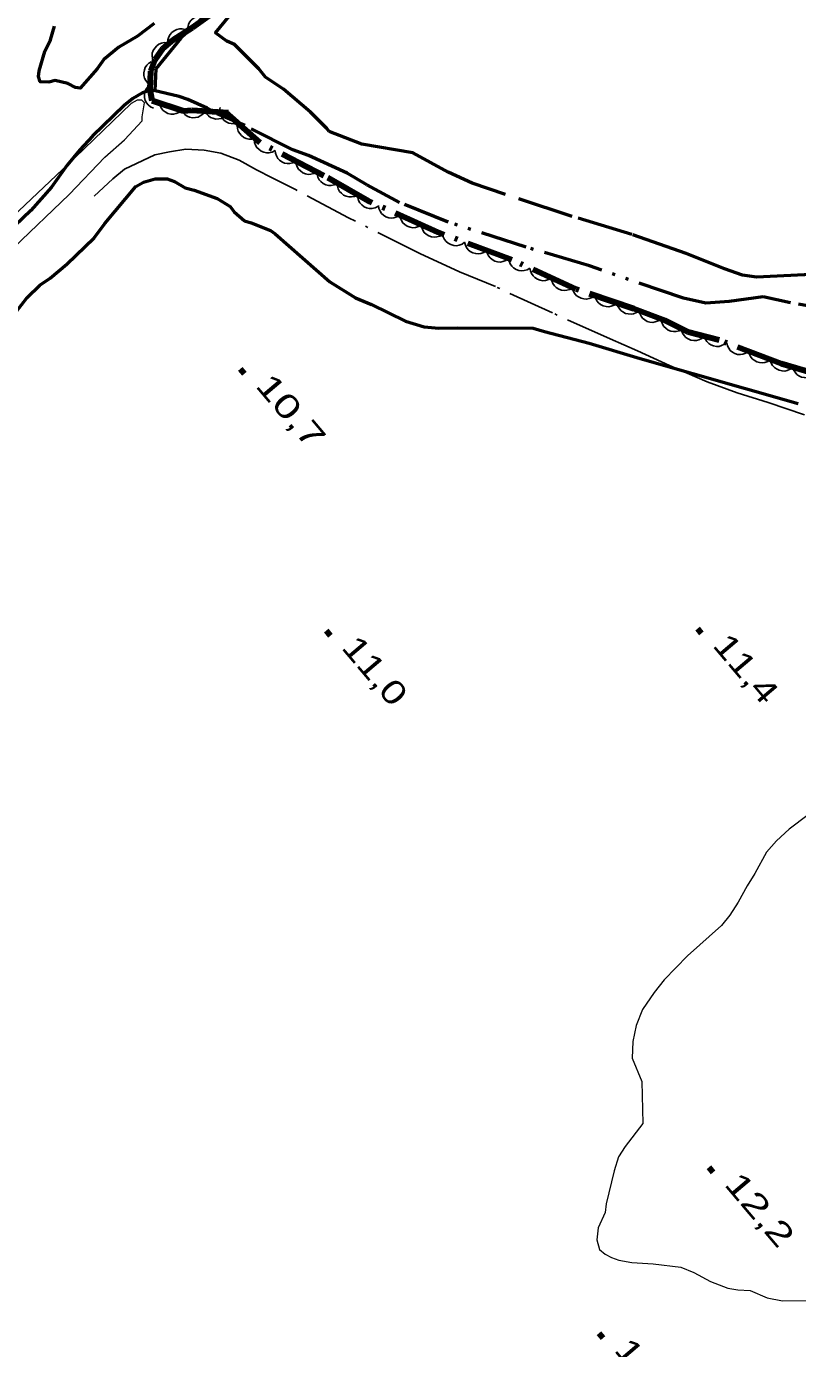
# Model space of a CAD drawing. Extents: x 386081 to 389416, y 5130568 to 5134082.
# Drawn here: x 387029 to 387127.7, y 5132295.3 to 5132464.6 of the extents above; entities that cross this region are included whole.
import ezdxf

# ---------------------------------------------------------------- set-up
doc = ezdxf.new("R2010")
doc.units = 0
doc.header["$LTSCALE"] = 1.2
for name, pattern in [('DASH_DOUBLE_DOT', [9.2, 5, -1.2, 0.3, -1.2, 0.3, -1.2]), ('DOT_DASHED', [7.7, 5, -1.2, 0.3, -1.2]), ('LONG_DASHED', [7.5, 6, -1.5])]:
    doc.linetypes.add(name, pattern=pattern)
for name, color, linetype, lineweight in [('1', 7, 'Continuous', 53), ('2', 7, 'Continuous', 13), ('3', 7, 'Continuous', 140), ('4', 7, 'DASH_DOUBLE_DOT', 53), ('41', 7, 'DOT_DASHED', 25), ('44', 7, 'Continuous', 25)]:
    doc.layers.add(name, color=color, linetype=linetype, lineweight=lineweight)

msp = doc.modelspace()

# ---------------------------------------------------------------- linework, layer by layer
at = {"layer": '1'}
for points in [[(387067.73, 5132451.13), (387067.44, 5132451.51), (387065.37, 5132453.59), (387061.92, 5132456.55), (387059.61, 5132458.09), (387058.74, 5132459.16), (387055.63, 5132462.28), (387054.67, 5132462.68), (387053.22, 5132463.76), (387056.77, 5132468.15)], [(387045.34, 5132464.97), (387043.24, 5132463.34), (387040.83, 5132461.92), (387038.92, 5132460.34), (387038.07, 5132459.17), (387035.9, 5132456.67), (387035.3, 5132456.78), (387034.31, 5132457.28), (387032.69, 5132457.67), (387031.86, 5132457.45), (387030.75, 5132457.51), (387030.54, 5132458.16), (387030.63, 5132458.91), (387031.35, 5132461.38), (387032.1, 5132462.88), (387032.6, 5132464.63)], [(387026.94, 5132427.05), (387029.08, 5132429.87), (387030.7, 5132431.47), (387032.05, 5132432.36), (387034.18, 5132434.15), (387037.66, 5132437.51), (387039.03, 5132439.34), (387043.02, 5132444.11), (387043.97, 5132444.65), (387045.48, 5132445.08), (387047, 5132445.07), (387047.94, 5132444.73)], [(387047.94, 5132444.73), (387049.31, 5132443.9), (387050.49, 5132443.61), (387053.4, 5132442.55), (387055.07, 5132441.54), (387055.57, 5132440.86), (387056.9, 5132439.7), (387057.77, 5132439.46), (387060.22, 5132438.47), (387060.84, 5132438.05), (387067.85, 5132431.87), (387071.11, 5132429.84), (387073.18, 5132428.99), (387077.5, 5132426.87), (387079.91, 5132426.13), (387081.8, 5132425.94), (387084.14, 5132426.01), (387093.87, 5132425.95), (387095.29, 5132425.51), (387101.02, 5132424.05), (387107.54, 5132422.08), (387127.76, 5132416.3)]]:
    msp.add_lwpolyline(points, dxfattribs=at)
at = {"layer": '1', "linetype": 'LONG_DASHED'}
msp.add_lwpolyline([(387145.13, 5132434.28), (387144.46, 5132434.47), (387140.66, 5132435.13), (387139.03, 5132435.07), (387137.56, 5132434.7), (387135.1, 5132433.76), (387132.87, 5132433.3), (387128.58, 5132432.8), (387122.45, 5132432.47), (387120.64, 5132432.76), (387118.34, 5132433.54), (387113.42, 5132435.51), (387106.5, 5132437.95), (387098.86, 5132440.25), (387086.03, 5132444.5), (387082.98, 5132445.94), (387078.46, 5132448.4), (387071.94, 5132449.51), (387067.73, 5132451.13)], dxfattribs=at)
at = {"layer": '2'}
for points in [[(387027.36, 5132436.24), (387034.46, 5132443.05), (387039.02, 5132447.86), (387041.54, 5132450.08), (387043.8, 5132452.5), (387043.81, 5132452.99), (387044.12, 5132454.79), (387043.79, 5132455.16), (387043.19, 5132455.16), (387042.39, 5132454.73), (387035.25, 5132447.8), (387022.35, 5132435.63)], [(387131.47, 5132365.48), (387126.61, 5132361.81), (387124.99, 5132360.33), (387123.74, 5132358.86), (387122.23, 5132356.15), (387121.23, 5132354.56), (387120.1, 5132352.46), (387119.04, 5132350.8), (387117.97, 5132349.51), (387113.61, 5132345.59), (387110.61, 5132342.52), (387109.36, 5132340.93), (387107.86, 5132338.72), (387107.04, 5132336.68), (387106.6, 5132334.65), (387106.52, 5132332.49), (387107.75, 5132329.52), (387107.9, 5132324.16), (387105.65, 5132321.21), (387104.78, 5132319.86), (387104.21, 5132318.07), (387103.19, 5132313.88), (387103.06, 5132312.77), (387102.18, 5132310.8), (387101.99, 5132309.26), (387102.35, 5132308.03), (387103.09, 5132307.41), (387103.9, 5132306.97), (387104.83, 5132306.65), (387106.5, 5132306.34), (387109.23, 5132306.19), (387112.76, 5132305.74), (387114.44, 5132305.05), (387116.54, 5132303.93), (387118.77, 5132303.05), (387120.07, 5132302.86), (387121.62, 5132302.78), (387123.79, 5132301.84), (387125.77, 5132301.46), (387129.19, 5132301.5)]]:
    msp.add_lwpolyline(points, dxfattribs=at)
at = {"layer": '3'}
for p, q in [((387056.36, 5132420.77), (387056.87, 5132420.16)), ((387067.37, 5132387.24), (387067.88, 5132386.63)), ((387114.87, 5132387.52), (387115.38, 5132386.91)), ((387116.36, 5132318.54), (387116.87, 5132317.93)), ((387102.27, 5132297.32), (387102.78, 5132296.71))]:
    msp.add_line(p, q, dxfattribs=at)
at = {"layer": '4'}
for points in [[(387174.18, 5132581.15), (387161.07, 5132568.63), (387130.69, 5132540.73), (387102.05, 5132513.97), (387076.72, 5132489.82), (387058.11, 5132471.82), (387048.75, 5132463.08), (387045.55, 5132459.16), (387045.43, 5132456.35)], [(387133.74, 5132427.94), (387126.78, 5132429.21), (387123.3, 5132429.98), (387118.94, 5132429.38), (387115.96, 5132429.15), (387113.1, 5132429.78), (387101.05, 5132433.93), (387092.98, 5132436.32), (387082.97, 5132439.54), (387076.77, 5132442.05), (387072.55, 5132444.3), (387070.07, 5132445.8), (387065.11, 5132448.05), (387063.12, 5132448.8), (387056.96, 5132451.88), (387053.43, 5132453.39), (387052.15, 5132454.12), (387049.66, 5132455.24), (387048.55, 5132455.62), (387045.32, 5132456.38), (387044.63, 5132456.32), (387043.88, 5132456.08), (387042.64, 5132455.34), (387041.51, 5132454.48), (387037.47, 5132450.52), (387035.84, 5132448.79), (387034.21, 5132446.82), (387032.21, 5132443.99), (387029.58, 5132441.03), (387025.39, 5132437.03)]]:
    msp.add_lwpolyline(points, dxfattribs=at)
at = {"layer": '41'}
msp.add_lwpolyline([(387128.59, 5132414.87), (387123.94, 5132416.43), (387119.97, 5132417.69), (387116.13, 5132419.07), (387111.29, 5132421.19), (387107.2, 5132423.07), (387103.73, 5132424.57), (387096.34, 5132427.9), (387089.03, 5132431.27), (387084.44, 5132433.15), (387079.36, 5132435.53), (387070.24, 5132440.1), (387063.42, 5132443.72), (387060.45, 5132445.22), (387058.46, 5132446.22), (387056.23, 5132447.47), (387053.88, 5132448.35), (387051.77, 5132448.73), (387049.41, 5132448.87), (387047.3, 5132448.51), (387045.43, 5132448.14), (387041.57, 5132446.31), (387040.07, 5132445.08), (387037.66, 5132442.85)], dxfattribs=at)
at = {"layer": '44', "linetype": 'DOT_DASHED', "lineweight": 90}
for points in [[(387054.84, 5132453.54), (387050.16, 5132453.8), (387049.1, 5132453.74), (387045.11, 5132455.05), (387044.84, 5132456.49), (387044.93, 5132458.84), (387045.48, 5132460.34), (387046.46, 5132461.74), (387047.79, 5132462.88), (387050.26, 5132464.45), (387056.3, 5132468.74), (387074.01, 5132485.29), (387109.85, 5132517.99), (387111.37, 5132518.92), (387113.6, 5132520.67), (387114.92, 5132522.09), (387116.83, 5132524.61), (387126.87, 5132537.21), (387128.69, 5132538.8)], [(387129.84, 5132420.15), (387125.62, 5132421.41), (387117.68, 5132424.42), (387113.7, 5132425.43), (387110.73, 5132426.93), (387106.76, 5132428.43), (387099.31, 5132430.95), (387091.13, 5132434.7), (387081.7, 5132438.21), (387072.78, 5132442.21), (387067.08, 5132445.46), (387058.9, 5132449.7), (387054.54, 5132453.55)]]:
    msp.add_lwpolyline(points, dxfattribs=at)
at = {"layer": '44'}
for points in [[(387049.65, 5132464.02), (387049.64, 5132464.43), (387049.75, 5132464.82), (387049.88, 5132465.13), (387050.1, 5132465.4), (387050.38, 5132465.64), (387050.73, 5132465.8), (387051.04, 5132465.91), (387051.39, 5132465.93), (387051.76, 5132465.88), (387052.09, 5132465.75)], [(387047.09, 5132462.44), (387047.11, 5132462.86), (387047.24, 5132463.24), (387047.38, 5132463.54), (387047.62, 5132463.8), (387047.91, 5132464.02), (387048.27, 5132464.17), (387048.58, 5132464.26), (387048.93, 5132464.26), (387049.3, 5132464.19), (387049.63, 5132464.05)], [(387045.27, 5132460.04), (387045.12, 5132460.43), (387045.09, 5132460.84), (387045.11, 5132461.17), (387045.24, 5132461.5), (387045.42, 5132461.82), (387045.69, 5132462.09), (387045.94, 5132462.3), (387046.27, 5132462.43), (387046.63, 5132462.51), (387046.99, 5132462.5)], [(387044.86, 5132457.08), (387044.53, 5132457.32), (387044.28, 5132457.65), (387044.12, 5132457.94), (387044.04, 5132458.28), (387044.03, 5132458.65), (387044.1, 5132459.02), (387044.2, 5132459.33), (387044.41, 5132459.62), (387044.67, 5132459.88), (387044.98, 5132460.07)], [(387045.28, 5132454.12), (387044.9, 5132454.28), (387044.59, 5132454.55), (387044.37, 5132454.79), (387044.22, 5132455.11), (387044.12, 5132455.47), (387044.11, 5132455.85), (387044.14, 5132456.17), (387044.28, 5132456.5), (387044.48, 5132456.81), (387044.73, 5132457.07)], [(387048.86, 5132453.82), (387048.53, 5132453.56), (387048.15, 5132453.42), (387047.83, 5132453.34), (387047.48, 5132453.36), (387047.12, 5132453.45), (387046.78, 5132453.63), (387046.51, 5132453.81), (387046.29, 5132454.08), (387046.11, 5132454.41), (387046.01, 5132454.75)], [(387051.84, 5132453.71), (387051.59, 5132453.37), (387051.26, 5132453.14), (387050.97, 5132452.98), (387050.63, 5132452.91), (387050.26, 5132452.9), (387049.88, 5132452.98), (387049.57, 5132453.09), (387049.29, 5132453.3), (387049.03, 5132453.56), (387048.85, 5132453.87)], [(387054.84, 5132453.54), (387054.59, 5132453.21), (387054.26, 5132452.97), (387053.97, 5132452.81), (387053.62, 5132452.74), (387053.25, 5132452.73), (387052.88, 5132452.82), (387052.57, 5132452.92), (387052.29, 5132453.13), (387052.03, 5132453.4), (387051.84, 5132453.71)], [(387056.03, 5132452.24), (387055.62, 5132452.13), (387055.22, 5132452.15), (387054.89, 5132452.21), (387054.58, 5132452.36), (387054.28, 5132452.58), (387054.04, 5132452.88), (387053.86, 5132453.16), (387053.77, 5132453.5), (387053.73, 5132453.86), (387053.78, 5132454.22)], [(387058.28, 5132450.25), (387057.87, 5132450.15), (387057.47, 5132450.16), (387057.14, 5132450.22), (387056.83, 5132450.38), (387056.53, 5132450.6), (387056.29, 5132450.9), (387056.11, 5132451.17), (387056.02, 5132451.51), (387055.98, 5132451.88), (387056.03, 5132452.24)], [(387060.83, 5132448.7), (387060.46, 5132448.5), (387060.06, 5132448.42), (387059.73, 5132448.4), (387059.39, 5132448.47), (387059.05, 5132448.62), (387058.74, 5132448.85), (387058.5, 5132449.07), (387058.33, 5132449.38), (387058.2, 5132449.73), (387058.16, 5132450.08)], [(387063.49, 5132447.32), (387063.12, 5132447.12), (387062.72, 5132447.04), (387062.39, 5132447.02), (387062.05, 5132447.09), (387061.71, 5132447.23), (387061.4, 5132447.47), (387061.16, 5132447.69), (387060.99, 5132448), (387060.87, 5132448.34), (387060.83, 5132448.7)], [(387066.15, 5132445.94), (387065.79, 5132445.74), (387065.39, 5132445.66), (387065.06, 5132445.64), (387064.71, 5132445.71), (387064.37, 5132445.85), (387064.07, 5132446.08), (387063.83, 5132446.31), (387063.66, 5132446.62), (387063.53, 5132446.96), (387063.49, 5132447.32)], [(387068.78, 5132444.49), (387068.4, 5132444.31), (387068, 5132444.24), (387067.67, 5132444.23), (387067.33, 5132444.32), (387067, 5132444.48), (387066.7, 5132444.72), (387066.47, 5132444.95), (387066.31, 5132445.27), (387066.2, 5132445.62), (387066.17, 5132445.98)], [(387071.38, 5132443.01), (387071.01, 5132442.82), (387070.61, 5132442.76), (387070.28, 5132442.75), (387069.94, 5132442.84), (387069.6, 5132442.99), (387069.31, 5132443.23), (387069.08, 5132443.46), (387068.92, 5132443.78), (387068.81, 5132444.13), (387068.78, 5132444.49)], [(387073.99, 5132441.52), (387073.62, 5132441.34), (387073.21, 5132441.27), (387072.88, 5132441.26), (387072.54, 5132441.35), (387072.21, 5132441.5), (387071.91, 5132441.75), (387071.68, 5132441.98), (387071.52, 5132442.29), (387071.41, 5132442.65), (387071.38, 5132443.01)], [(387076.79, 5132440.41), (387076.43, 5132440.19), (387076.04, 5132440.09), (387075.71, 5132440.05), (387075.37, 5132440.1), (387075.02, 5132440.22), (387074.7, 5132440.44), (387074.45, 5132440.65), (387074.26, 5132440.94), (387074.11, 5132441.29), (387074.05, 5132441.64)], [(387079.53, 5132439.18), (387079.17, 5132438.96), (387078.78, 5132438.86), (387078.45, 5132438.82), (387078.1, 5132438.88), (387077.75, 5132439), (387077.44, 5132439.21), (387077.19, 5132439.42), (387077, 5132439.72), (387076.85, 5132440.06), (387076.79, 5132440.41)], [(387082.26, 5132437.96), (387081.91, 5132437.74), (387081.52, 5132437.63), (387081.19, 5132437.59), (387080.84, 5132437.65), (387080.49, 5132437.77), (387080.17, 5132437.98), (387079.92, 5132438.19), (387079.73, 5132438.49), (387079.59, 5132438.83), (387079.53, 5132439.18)], [(387085.09, 5132436.95), (387084.75, 5132436.71), (387084.37, 5132436.58), (387084.04, 5132436.51), (387083.69, 5132436.55), (387083.33, 5132436.65), (387083, 5132436.84), (387082.74, 5132437.03), (387082.53, 5132437.31), (387082.36, 5132437.64), (387082.28, 5132437.99)], [(387087.9, 5132435.9), (387087.56, 5132435.66), (387087.18, 5132435.53), (387086.85, 5132435.47), (387086.5, 5132435.5), (387086.15, 5132435.6), (387085.81, 5132435.79), (387085.55, 5132435.98), (387085.34, 5132436.27), (387085.18, 5132436.6), (387085.09, 5132436.95)], [(387090.71, 5132434.86), (387090.37, 5132434.61), (387089.99, 5132434.48), (387089.66, 5132434.42), (387089.31, 5132434.45), (387088.96, 5132434.55), (387088.63, 5132434.74), (387088.36, 5132434.94), (387088.15, 5132435.22), (387087.99, 5132435.55), (387087.9, 5132435.9)], [(387093.45, 5132433.63), (387093.1, 5132433.42), (387092.7, 5132433.32), (387092.37, 5132433.28), (387092.03, 5132433.34), (387091.68, 5132433.46), (387091.36, 5132433.68), (387091.11, 5132433.89), (387090.93, 5132434.19), (387090.79, 5132434.53), (387090.73, 5132434.89)], [(387096.18, 5132432.38), (387095.82, 5132432.17), (387095.43, 5132432.07), (387095.1, 5132432.03), (387094.75, 5132432.09), (387094.41, 5132432.21), (387094.09, 5132432.43), (387093.84, 5132432.64), (387093.65, 5132432.94), (387093.51, 5132433.28), (387093.45, 5132433.63)], [(387098.91, 5132431.13), (387098.55, 5132430.92), (387098.16, 5132430.82), (387097.83, 5132430.78), (387097.48, 5132430.84), (387097.13, 5132430.96), (387096.82, 5132431.18), (387096.57, 5132431.39), (387096.38, 5132431.69), (387096.24, 5132432.03), (387096.18, 5132432.38)], [(387101.73, 5132430.13), (387101.4, 5132429.88), (387101.02, 5132429.74), (387100.7, 5132429.66), (387100.35, 5132429.69), (387099.99, 5132429.78), (387099.65, 5132429.96), (387099.38, 5132430.14), (387099.16, 5132430.42), (387098.99, 5132430.74), (387098.89, 5132431.09)], [(387104.57, 5132429.17), (387104.24, 5132428.92), (387103.86, 5132428.78), (387103.54, 5132428.7), (387103.19, 5132428.73), (387102.83, 5132428.81), (387102.49, 5132429), (387102.22, 5132429.18), (387102.01, 5132429.46), (387101.83, 5132429.78), (387101.73, 5132430.13)], [(387107.42, 5132428.21), (387107.08, 5132427.96), (387106.7, 5132427.81), (387106.38, 5132427.74), (387106.03, 5132427.77), (387105.67, 5132427.85), (387105.33, 5132428.03), (387105.06, 5132428.22), (387104.85, 5132428.5), (387104.67, 5132428.82), (387104.57, 5132429.17)], [(387110.21, 5132427.12), (387109.87, 5132426.88), (387109.49, 5132426.76), (387109.16, 5132426.69), (387108.81, 5132426.73), (387108.46, 5132426.83), (387108.13, 5132427.02), (387107.86, 5132427.22), (387107.66, 5132427.5), (387107.49, 5132427.84), (387107.41, 5132428.19)], [(387112.92, 5132425.83), (387112.55, 5132425.62), (387112.15, 5132425.54), (387111.82, 5132425.51), (387111.48, 5132425.58), (387111.14, 5132425.72), (387110.83, 5132425.95), (387110.59, 5132426.17), (387110.41, 5132426.47), (387110.28, 5132426.82), (387110.24, 5132427.18)], [(387115.76, 5132424.91), (387115.44, 5132424.63), (387115.07, 5132424.46), (387114.76, 5132424.36), (387114.41, 5132424.36), (387114.04, 5132424.42), (387113.69, 5132424.57), (387113.41, 5132424.74), (387113.17, 5132425), (387112.97, 5132425.31), (387112.85, 5132425.65)], [(387118.66, 5132424.17), (387118.35, 5132423.89), (387117.98, 5132423.72), (387117.67, 5132423.62), (387117.32, 5132423.62), (387116.95, 5132423.68), (387116.6, 5132423.84), (387116.32, 5132424), (387116.08, 5132424.26), (387115.88, 5132424.57), (387115.76, 5132424.91)], [(387121.43, 5132423), (387121.09, 5132422.76), (387120.71, 5132422.63), (387120.38, 5132422.57), (387120.03, 5132422.6), (387119.68, 5132422.7), (387119.35, 5132422.9), (387119.08, 5132423.09), (387118.88, 5132423.38), (387118.71, 5132423.71), (387118.63, 5132424.06)], [(387124.24, 5132421.93), (387123.9, 5132421.69), (387123.51, 5132421.57), (387123.19, 5132421.5), (387122.84, 5132421.54), (387122.48, 5132421.64), (387122.15, 5132421.84), (387121.89, 5132422.03), (387121.68, 5132422.31), (387121.52, 5132422.65), (387121.43, 5132423)], [(387127.08, 5132420.97), (387126.76, 5132420.71), (387126.38, 5132420.55), (387126.06, 5132420.47), (387125.71, 5132420.48), (387125.35, 5132420.56), (387125, 5132420.73), (387124.73, 5132420.9), (387124.5, 5132421.17), (387124.31, 5132421.49), (387124.21, 5132421.83)], [(387129.95, 5132420.12), (387129.63, 5132419.85), (387129.26, 5132419.7), (387128.94, 5132419.61), (387128.58, 5132419.62), (387128.22, 5132419.7), (387127.88, 5132419.87), (387127.6, 5132420.04), (387127.38, 5132420.31), (387127.19, 5132420.63), (387127.08, 5132420.97)]]:
    msp.add_lwpolyline(points, dxfattribs=at)

# ---------------------------------------------------------------- texts
at = {"layer": '3'}
for s, width, p in [('10,7   ', 1.4, (387058.19, 5132418.55)), ('11,0   ', 1.3, (387069.2, 5132385.02)), ('11,4   ', 1.3, (387116.7, 5132385.3)), ('12,2   ', 1.4, (387118.19, 5132316.32)), ('11,8   ', 1.3, (387104.1, 5132295.1))]:
    msp.add_text(s, height=3, rotation=310.294, dxfattribs=dict(at, width=width)).set_placement(p)

doc.saveas('drawing.dxf')
